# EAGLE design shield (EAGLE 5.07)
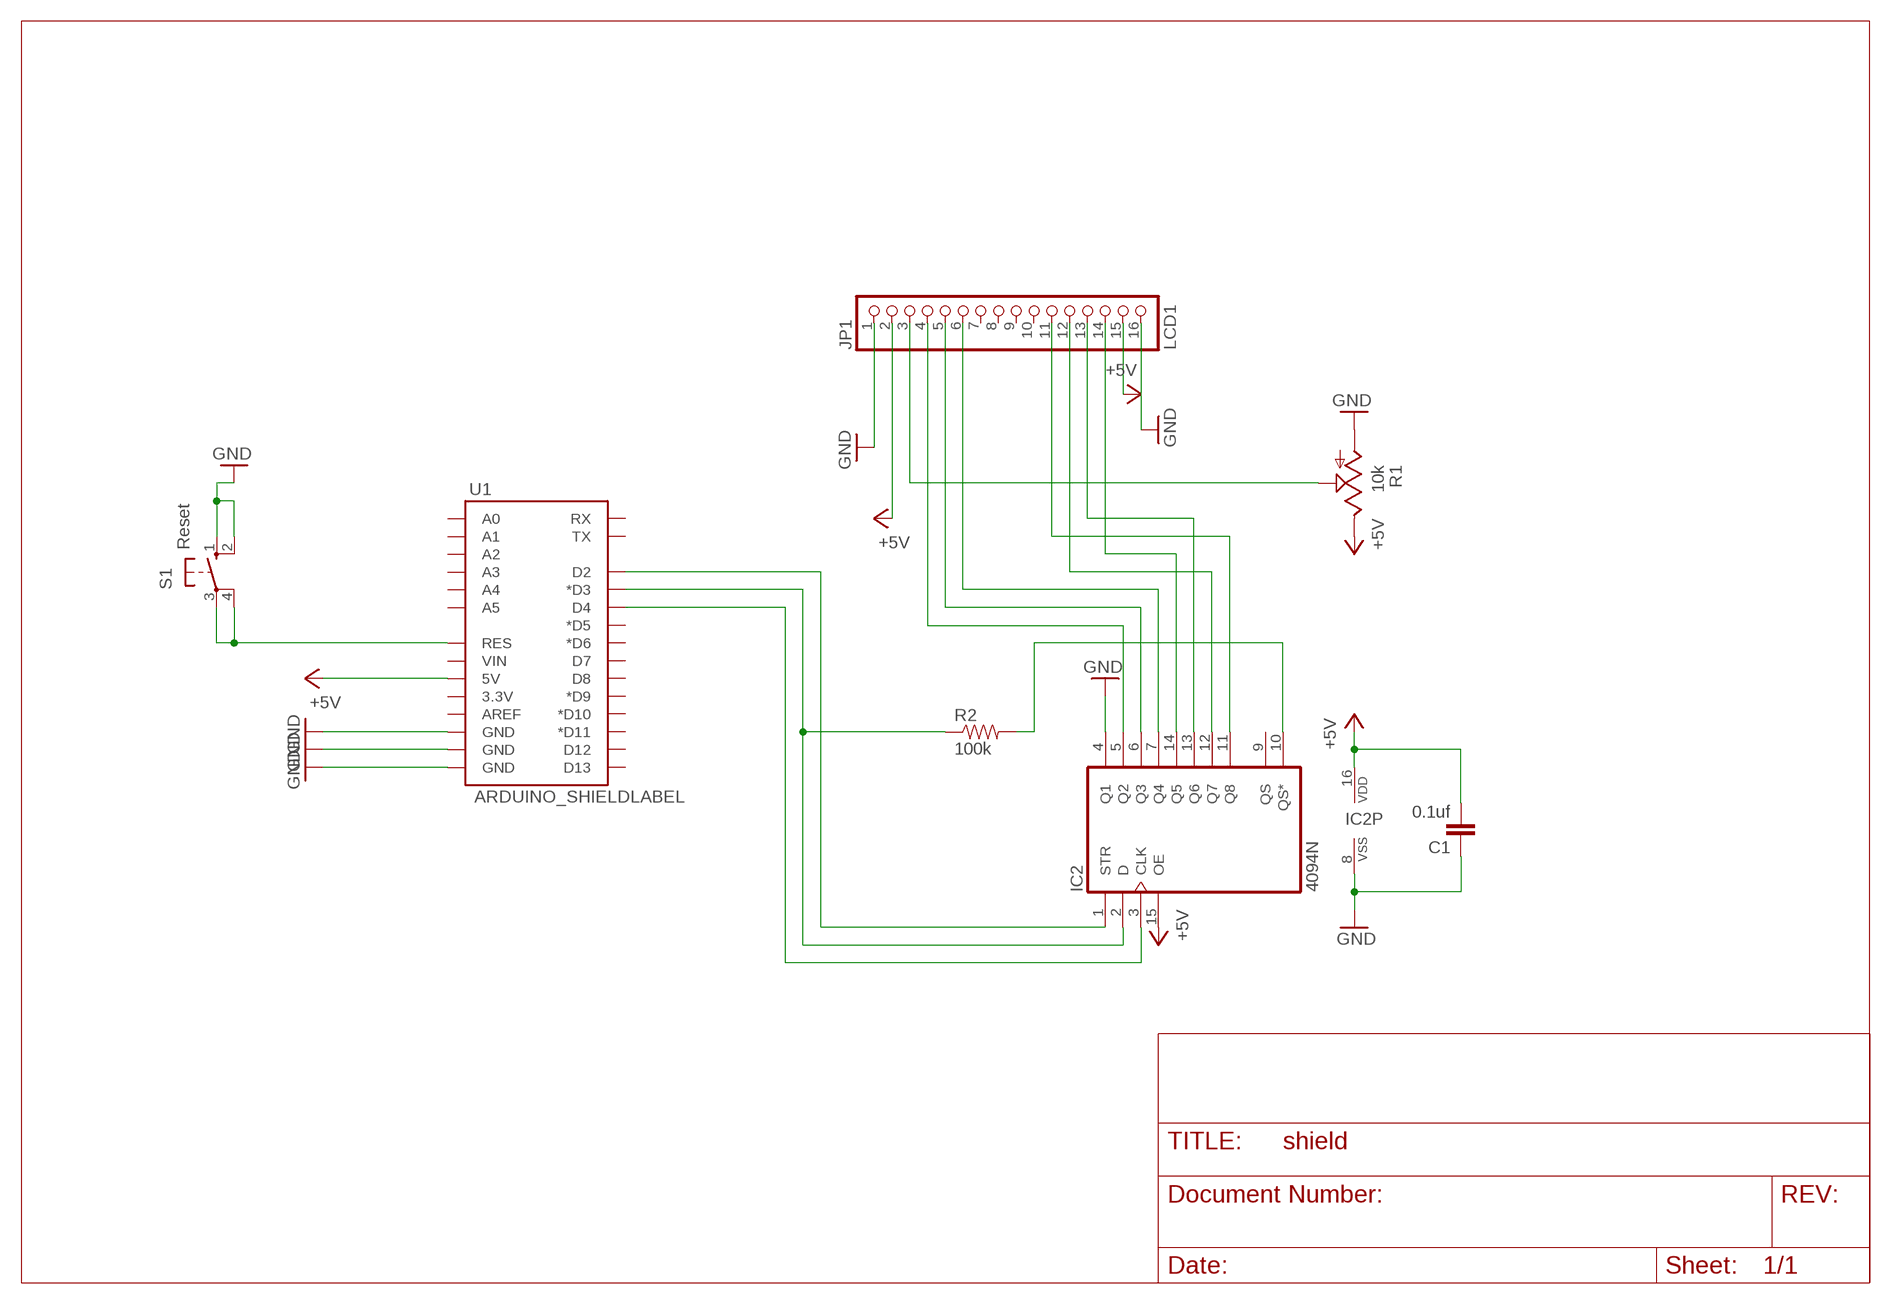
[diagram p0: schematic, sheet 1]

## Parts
C1  0.1uf  C2.5/2  [C2.5-2]
IC2  4094N  [DIL16]
JP1  LCD1  PINHD-1X16  [1X16]
R1  10k  TRIM_US-RS3  [RS3]
R2  100k  RESISTORPTH1  [AXIAL-0.3]
S1  Reset  10-XX  [B3F-10XX]
U1  ARDUINO_SHIELDLABEL  [DUEMILANOVE_SHIELD]

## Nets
+5V: C1.2 IC2.15(OE) IC2.16(VDD) JP1.2 JP1.15 R1.E U1.5V
GND: C1.1 IC2.4(Q1) IC2.8(VSS) JP1.1 JP1.16 R1.A S1.1(S) S1.2(S1) U1.GND@0(GND) U1.GND@1(GND) U1.GND@2(GND)
N$1: JP1.3 R1.S
N$2: IC2.5(Q2) JP1.4
N$3: IC2.6(Q3) JP1.5
N$4: IC2.7(Q4) JP1.6
N$5: IC2.14(Q5) JP1.14
N$6: IC2.13(Q6) JP1.13
N$7: IC2.12(Q7) JP1.12
N$8: IC2.11(Q8) JP1.11
N$9: IC2.1(STR) U1.D2
N$10: IC2.2(D) R2.P$1 U1.D3(*D3)
N$11: IC2.3(CLK) U1.D4
N$12: IC2.10(QS*) R2.P$2
N$13: S1.3(P) S1.4(P1) U1.RES
Unconnected: IC2.9(QS) JP1.7 JP1.8 JP1.9 JP1.10 U1.3.3V U1.A0 U1.A1 U1.A2 U1.A3 U1.A4 U1.A5 U1.AREF U1.D5(*D5) U1.D6(*D6) U1.D7 U1.D8 U1.D9(*D9) U1.D10(*D10) U1.D11(*D11) U1.D12 U1.D13 U1.RX U1.TX U1.VIN

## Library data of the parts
C1 = capacitor-wima:C: CAPACITOR
IC2 = 40xx:4094: 8-stage SHIFT/STORE REGISTER, tri-state
JP1 = pinhead:PINHD-1X16: PIN HEADER
R1 = pot:TRIM_US-: POTENTIOMETER
R2 = SparkFun:RESISTOR: Resistor
S1 = switch-omron:10-XX: OMRON SWITCH
U1 = SparkFun:ARDUINO_SHIELD

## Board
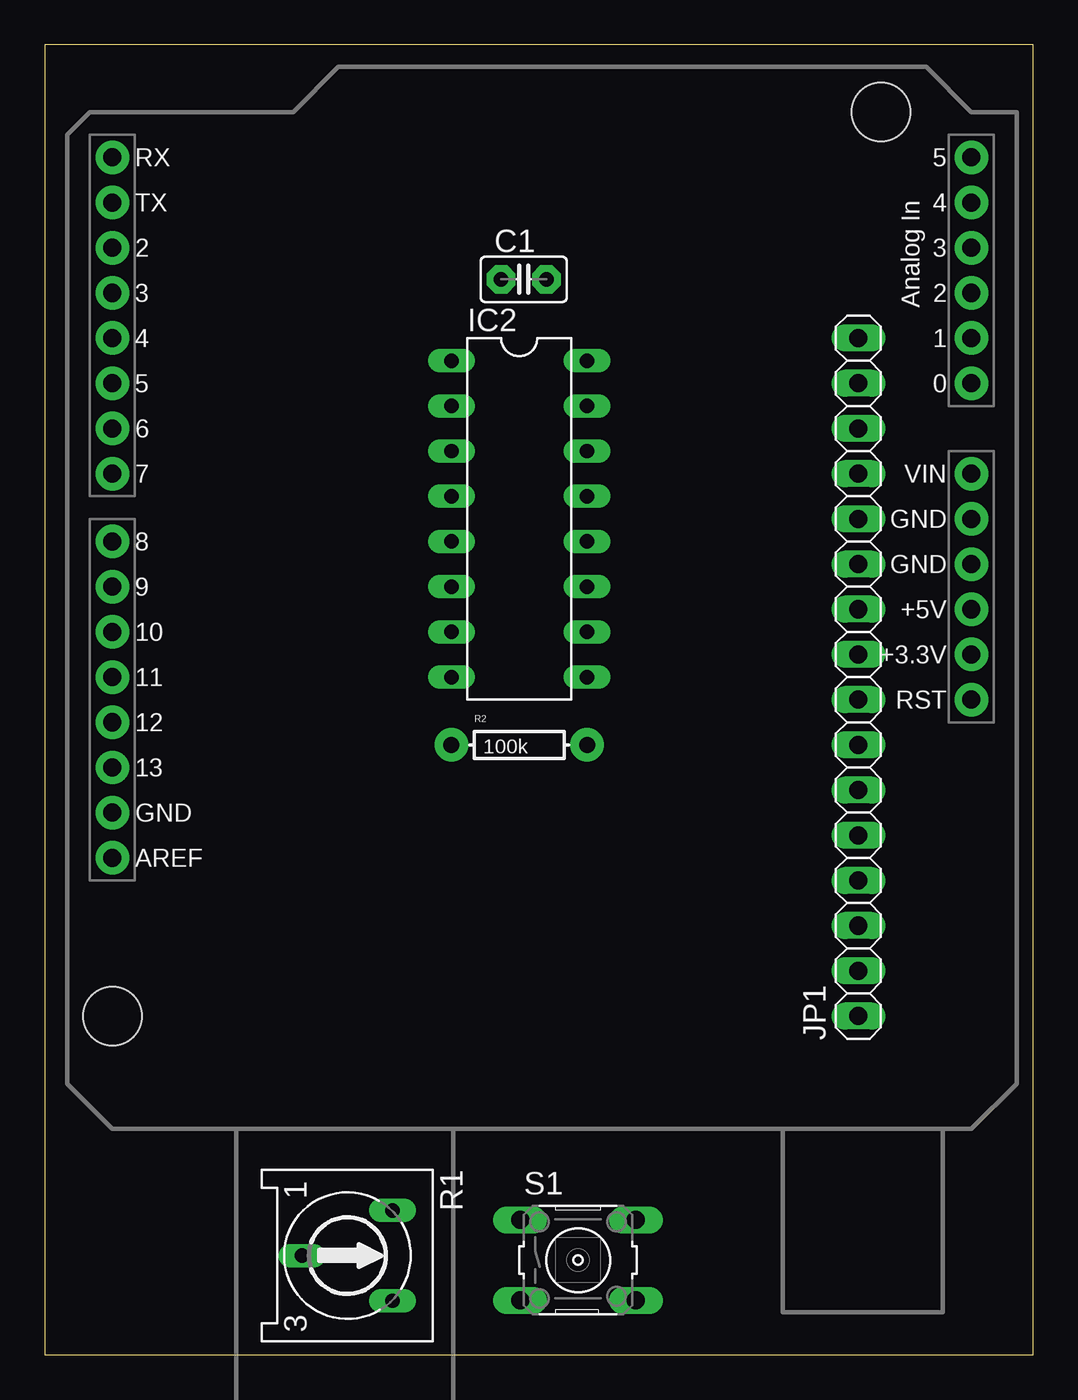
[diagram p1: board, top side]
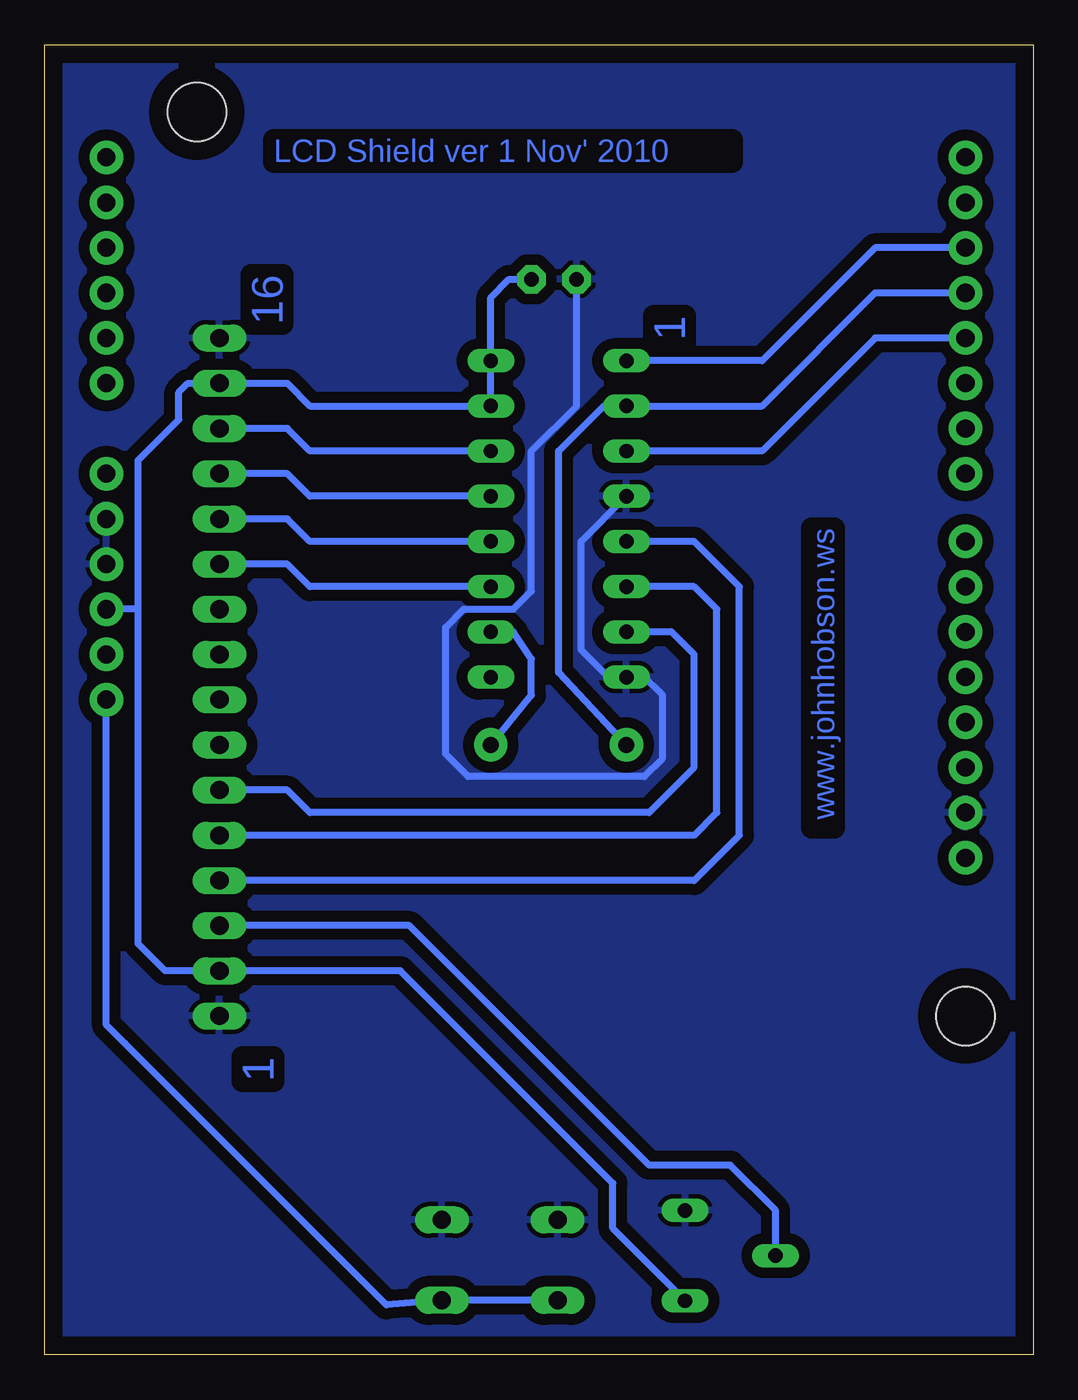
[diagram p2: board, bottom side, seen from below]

Size 55.55 x 73.65 mm. Coordinates in mm from the lower left corner, seen from the top.
Outline: 0,0 55.55,0 55.55,73.65 0,73.65 0,0
Copper layers (1*16): Top 0.035mm / dielectric 1.5mm / Bottom 0.035mm
Design rules "default": minimum track width 10mil, minimum drill 24mil, track to track 8mil, track to pad 8mil, pad to pad 8mil, via to via 8mil, smd to smd 8mil, copper to edge 40mil, drill to drill 8mil, minimum pad ring 10mil, minimum via ring 8mil, stop-mask expansion 4mil, vias tented up to drill 0mil, thermal gap 10mil

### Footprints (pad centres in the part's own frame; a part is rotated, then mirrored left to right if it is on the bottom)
C2.5-2 = drill 0.813 pad 1.6 octagon: 1 -1.27,0; 2 1.27,0
DIL16 = drill 0.813 long: 1 -8.89,-3.81; 2 -6.35,-3.81; 3 -3.81,-3.81; 4 -1.27,-3.81; 5 1.27,-3.81; 6 3.81,-3.81; 7 6.35,-3.81; 8 8.89,-3.81; 9 8.89,3.81; 10 6.35,3.81; 11 3.81,3.81; 12 1.27,3.81; 13 -1.27,3.81; 14 -3.81,3.81; 15 -6.35,3.81; 16 -8.89,3.81
1X16 = drill 1.016 long: 1 -19.05,0; 2 -16.51,0; 3 -13.97,0; 4 -11.43,0; 5 -8.89,0; 6 -6.35,0; 7 -3.81,0; 8 -1.27,0; 9 1.27,0; 10 3.81,0; 11 6.35,0; 12 8.89,0; 13 11.43,0; 14 13.97,0; 15 16.51,0; 16 19.05,0
RS3 = drill 0.813 long: A -2.54,2.54; E 2.54,2.54; S 0,-2.54
AXIAL-0.3 = drill 0.9 pad 1.88 round: P$1 -3.81,0; P$2 3.81,0
B3F-10XX = drill 1.016 long: 1 -3.251,2.261; 2 3.251,2.261; 3 -3.251,-2.261; 4 3.251,-2.261
DUEMILANOVE_SHIELD = drill 1.016 pad 1.88 round: 3.3V 50.8,26.67; 5V 50.8,29.21; A0 50.8,41.91; A1 50.8,44.45; A2 50.8,46.99; A3 50.8,49.53; A4 50.8,52.07; A5 50.8,54.61; AREF 2.54,15.24; D2 2.54,49.53; D3 2.54,46.99; D4 2.54,44.45; D5 2.54,41.91; D6 2.54,39.37; D7 2.54,36.83; D8 2.54,33.02; D9 2.54,30.48; D10 2.54,27.94; D11 2.54,25.4; D12 2.54,22.86; D13 2.54,20.32; GND@0 50.8,31.75; GND@1 50.8,34.29; GND@2 2.54,17.78; RES 50.8,24.13; RX 2.54,54.61; TX 2.54,52.07; VIN 50.8,36.83 | hole 3.302: 45.72,57.15; 2.54,6.35

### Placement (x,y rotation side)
C1  26.92,60.45 0 top
IC2  26.67,46.99 270 top
JP1  45.72,38.1 90 top
R1  17.02,5.59 270 top
R2  26.67,34.29 0 top
S1  29.97,5.33 0 top
U1  1.27,12.7 0 top

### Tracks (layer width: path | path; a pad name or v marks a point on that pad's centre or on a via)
+5V
  Bottom 0.406: 51.31,41.91 U1.5V 50.29,41.91 | 50.29,41.91 50.29,50.29 48.01,52.58 48.01,54.1 47.5,54.61 JP1.15 41.91,54.61 40.64,53.34 IC2.15 IC2.16 30.48,59.44 29.46,60.45 C1.2 | 50.29,41.91 50.29,23.11 48.77,21.59 JP1.2 35.56,21.59 23.62,9.65 23.62,7.11 R1.E
GND
  Bottom 0.406: IC2.4 25.4,45.72 25.4,39.62 23.88,38.1 IC2.8 21.84,38.1 20.83,37.08 20.83,33.53 21.84,32.51 31.75,32.51 33.02,33.78 33.02,40.89 32,41.91 29.21,41.91 28.19,42.93 28.19,50.8 25.65,53.34 C1.1
  pour Bottom (isolate 0.61): 0,73.66 55.63,73.66 55.63,0 0,0
N$1
  Bottom 0.406: JP1.3 35.05,24.13 21.59,10.67 17.02,10.67 14.48,8.13 R1.S
N$2
  Bottom 0.406: IC2.5 19.05,45.72 16.51,43.18 16.51,29.21 19.05,26.67 JP1.4
N$3
  Bottom 0.406: IC2.6 19.05,43.18 17.78,41.91 17.78,30.48 19.05,29.21 JP1.5
N$4
  Bottom 0.406: IC2.7 20.32,40.64 19.05,39.37 19.05,33.02 21.59,30.48 40.64,30.48 41.91,31.75 JP1.6
N$5
  Bottom 0.406: IC2.14 40.64,50.8 41.91,52.07 JP1.14
N$6
  Bottom 0.406: IC2.13 40.64,48.26 41.91,49.53 JP1.13
N$7
  Bottom 0.406: IC2.12 40.64,45.72 41.91,46.99 JP1.12
N$8
  Bottom 0.406: IC2.11 40.64,43.18 41.91,44.45 JP1.11
N$9
  Bottom 0.406: IC2.1 15.24,55.88 8.89,62.23 U1.D2
N$10
  Bottom 0.406: U1.D3 8.89,59.69 15.24,53.34 IC2.2 24.13,53.34 26.67,50.8 26.67,38.35 R2.P$1
N$11
  Bottom 0.406: U1.D4 8.89,57.15 15.24,50.8 IC2.3
N$12
  Bottom 0.406: IC2.10 29.21,40.64 28.19,39.12 28.19,37.08 R2.P$2
N$13
  Bottom 0.406: U1.RES 52.07,18.54 51.03,17.53 49.78,16.26 36.35,2.82 S1.4 S1.3

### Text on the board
Bottom: LCD Shield ver 1 Nov' 2010 | 16 | 1 | www.johnhobson.ws | 1 | 1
